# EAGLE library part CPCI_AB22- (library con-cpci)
Compact PCI AB 22 Source: www.erni.com
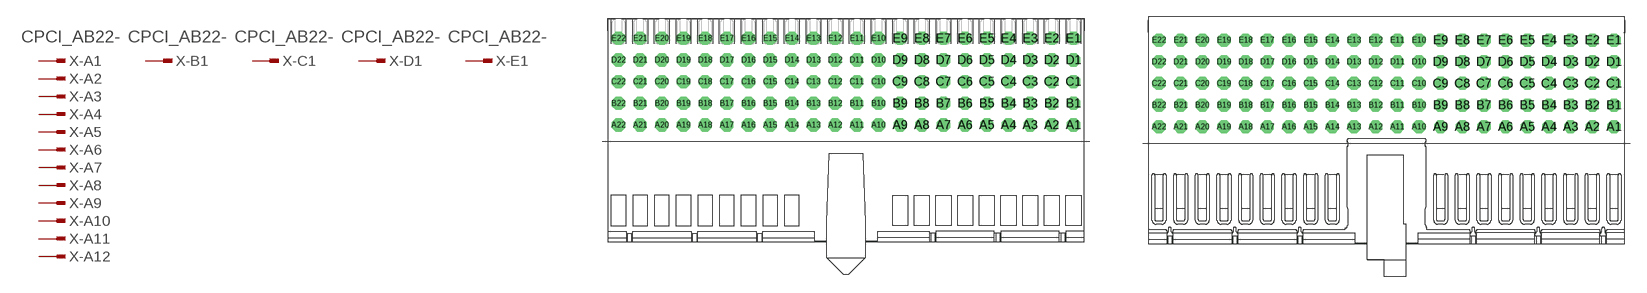
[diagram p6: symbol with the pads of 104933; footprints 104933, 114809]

Designator prefix X; gates -A1=PINV -B1=PINV -C1=PINV -D1=PINV -E1=PINV -A2=PIN -A3=PIN -A4=PIN -A5=PIN -A6=PIN -A7=PIN -A8=PIN -A9=PIN -A10=PIN -A11=PIN -A12=PIN -A13=PIN -A14=PIN -A15=PIN -A16=PIN -A17=PIN -A18=PIN -A19=PIN -A20=PIN -A21=PIN -A22=PIN -B2=PIN -B3=PIN -B4=PIN -B5=PIN -B6=PIN -B7=PIN -B8=PIN -B9=PIN -B10=PIN -B11=PIN -B12=PIN -B13=PIN -B14=PIN -B15=PIN -B16=PIN -B17=PIN -B18=PIN -B19=PIN -B20=PIN -B21=PIN -B22=PIN -C2=PIN -C3=PIN -C4=PIN -C5=PIN -C6=PIN -C7=PIN -C8=PIN -C9=PIN -C10=PIN -C11=PIN -C12=PIN -C13=PIN -C14=PIN -C15=PIN -C16=PIN -C17=PIN -C18=PIN -C19=PIN -C20=PIN -C21=PIN -C22=PIN -D2=PIN -D3=PIN -D4=PIN -D5=PIN -D6=PIN -D7=PIN -D8=PIN -D9=PIN -D10=PIN -D11=PIN -D12=PIN -D13=PIN -D14=PIN -D15=PIN -D16=PIN -D17=PIN -D18=PIN -D19=PIN -D20=PIN -D21=PIN -D22=PIN -E2=PIN -E3=PIN -E4=PIN -E5=PIN -E6=PIN -E7=PIN -E8=PIN -E9=PIN -E10=PIN -E11=PIN -E12=PIN -E13=PIN -E14=PIN -E15=PIN -E16=PIN -E17=PIN -E18=PIN -E19=PIN -E20=PIN -E21=PIN -E22=PIN

## CPCI_AB22-104933  [104933]
A1  -A1:1  in
A2  -A2:1  in
A3  -A3:1  in
A4  -A4:1  in
A5  -A5:1  in
A6  -A6:1  in
A7  -A7:1  in
A8  -A8:1  in
A9  -A9:1  in
A10  -A10:1  in
A11  -A11:1  in
A12  -A12:1  in
A13  -A13:1  in
A14  -A14:1  in
A15  -A15:1  in
A16  -A16:1  in
A17  -A17:1  in
A18  -A18:1  in
A19  -A19:1  in
A20  -A20:1  in
A21  -A21:1  in
A22  -A22:1  in
B1  -B1:1  in
B2  -B2:1  in
B3  -B3:1  in
B4  -B4:1  in
B5  -B5:1  in
B6  -B6:1  in
B7  -B7:1  in
B8  -B8:1  in
B9  -B9:1  in
B10  -B10:1  in
B11  -B11:1  in
B12  -B12:1  in
B13  -B13:1  in
B14  -B14:1  in
B15  -B15:1  in
B16  -B16:1  in
B17  -B17:1  in
B18  -B18:1  in
B19  -B19:1  in
B20  -B20:1  in
B21  -B21:1  in
B22  -B22:1  in
C1  -C1:1  in
C2  -C2:1  in
C3  -C3:1  in
C4  -C4:1  in
C5  -C5:1  in
C6  -C6:1  in
C7  -C7:1  in
C8  -C8:1  in
C9  -C9:1  in
C10  -C10:1  in
C11  -C11:1  in
C12  -C12:1  in
C13  -C13:1  in
C14  -C14:1  in
C15  -C15:1  in
C16  -C16:1  in
C17  -C17:1  in
C18  -C18:1  in
C19  -C19:1  in
C20  -C20:1  in
C21  -C21:1  in
C22  -C22:1  in
D1  -D1:1  in
D2  -D2:1  in
D3  -D3:1  in
D4  -D4:1  in
D5  -D5:1  in
D6  -D6:1  in
D7  -D7:1  in
D8  -D8:1  in
D9  -D9:1  in
D10  -D10:1  in
D11  -D11:1  in
D12  -D12:1  in
D13  -D13:1  in
D14  -D14:1  in
D15  -D15:1  in
D16  -D16:1  in
D17  -D17:1  in
D18  -D18:1  in
D19  -D19:1  in
D20  -D20:1  in
D21  -D21:1  in
D22  -D22:1  in
E1  -E1:1  in
E2  -E2:1  in
E3  -E3:1  in
E4  -E4:1  in
E5  -E5:1  in
E6  -E6:1  in
E7  -E7:1  in
E8  -E8:1  in
E9  -E9:1  in
E10  -E10:1  in
E11  -E11:1  in
E12  -E12:1  in
E13  -E13:1  in
E14  -E14:1  in
E15  -E15:1  in
E16  -E16:1  in
E17  -E17:1  in
E18  -E18:1  in
E19  -E19:1  in
E20  -E20:1  in
E21  -E21:1  in
E22  -E22:1  in

## CPCI_AB22-114809  [114809]
Pads as for 104933

## Footprint 104933 (pad centres in mm)
ERmet Federleiste AB 22 / ERmet Female Type AB 22 Source: http://www.erni.com/DB/PDF-Drawing/ERmet/104933.pdf
drill 0.7 pad 1.016 octagon: A1 21,1.5; A2 19,1.5; A3 17,1.5; A4 15,1.5; A5 13,1.5; A6 11,1.5; A7 9,1.5; A8 7,1.5; A9 5,1.5; A10 3,1.5; A11 1,1.5; A12 -1,1.5; A13 -3,1.5; A14 -5,1.5; A15 -7,1.5; A16 -9,1.5; A17 -11,1.5; A18 -13,1.5; A19 -15,1.5; A20 -17,1.5; A21 -19,1.5; A22 -21,1.5; B1 21,3.5; B2 19,3.5; B3 17,3.5; B4 15,3.5; B5 13,3.5; B6 11,3.5; B7 9,3.5; B8 7,3.5; B9 5,3.5; B10 3,3.5; B11 1,3.5; B12 -1,3.5; B13 -3,3.5; B14 -5,3.5; B15 -7,3.5; B16 -9,3.5; B17 -11,3.5; B18 -13,3.5; B19 -15,3.5; B20 -17,3.5; B21 -19,3.5; B22 -21,3.5; C1 21,5.5; C2 19,5.5; C3 17,5.5; C4 15,5.5; C5 13,5.5; C6 11,5.5; C7 9,5.5; C8 7,5.5; C9 5,5.5; C10 3,5.5; C11 1,5.5; C12 -1,5.5; C13 -3,5.5; C14 -5,5.5; C15 -7,5.5; C16 -9,5.5; C17 -11,5.5; C18 -13,5.5; C19 -15,5.5; C20 -17,5.5; C21 -19,5.5; C22 -21,5.5; D1 21,7.5; D2 19,7.5; D3 17,7.5; D4 15,7.5; D5 13,7.5; D6 11,7.5; D7 9,7.5; D8 7,7.5; D9 5,7.5; D10 3,7.5; D11 1,7.5; D12 -1,7.5; D13 -3,7.5; D14 -5,7.5; D15 -7,7.5; D16 -9,7.5; D17 -11,7.5; D18 -13,7.5; D19 -15,7.5; D20 -17,7.5; D21 -19,7.5; D22 -21,7.5; E1 21,9.5; E2 19,9.5; E3 17,9.5; E4 15,9.5; E5 13,9.5; E6 11,9.5; E7 9,9.5; E8 7,9.5; E9 5,9.5; E10 3,9.5; E11 1,9.5; E12 -1,9.5; E13 -3,9.5; E14 -5,9.5; E15 -7,9.5; E16 -9,9.5; E17 -11,9.5; E18 -13,9.5; E19 -15,9.5; E20 -17,9.5; E21 -19,9.5; E22 -21,9.5

## Footprint 114809 (pad centres in mm)
ERmet Federleiste AB 22 / ERmet Female Type AB 22 Source: http://www.erni.com/DB/PDF-Drawing/ERmet/114809.pdf
drill 0.7 pad 1.016 octagon: A1 189,-71.5; A2 187,-71.5; A3 185,-71.5; A4 183,-71.5; A5 181,-71.5; A6 179,-71.5; A7 177,-71.5; A8 175,-71.5; A9 173,-71.5; A10 171,-71.5; A11 169,-71.5; A12 167,-71.5; A13 165,-71.5; A14 163,-71.5; A15 161,-71.5; A16 159,-71.5; A17 157,-71.5; A18 155,-71.5; A19 153,-71.5; A20 151,-71.5; A21 149,-71.5; A22 147,-71.5; B1 189,-69.5; B2 187,-69.5; B3 185,-69.5; B4 183,-69.5; B5 181,-69.5; B6 179,-69.5; B7 177,-69.5; B8 175,-69.5; B9 173,-69.5; B10 171,-69.5; B11 169,-69.5; B12 167,-69.5; B13 165,-69.5; B14 163,-69.5; B15 161,-69.5; B16 159,-69.5; B17 157,-69.5; B18 155,-69.5; B19 153,-69.5; B20 151,-69.5; B21 149,-69.5; B22 147,-69.5; C1 189,-67.5; C2 187,-67.5; C3 185,-67.5; C4 183,-67.5; C5 181,-67.5; C6 179,-67.5; C7 177,-67.5; C8 175,-67.5; C9 173,-67.5; C10 171,-67.5; C11 169,-67.5; C12 167,-67.5; C13 165,-67.5; C14 163,-67.5; C15 161,-67.5; C16 159,-67.5; C17 157,-67.5; C18 155,-67.5; C19 153,-67.5; C20 151,-67.5; C21 149,-67.5; C22 147,-67.5; D1 189,-65.5; D2 187,-65.5; D3 185,-65.5; D4 183,-65.5; D5 181,-65.5; D6 179,-65.5; D7 177,-65.5; D8 175,-65.5; D9 173,-65.5; D10 171,-65.5; D11 169,-65.5; D12 167,-65.5; D13 165,-65.5; D14 163,-65.5; D15 161,-65.5; D16 159,-65.5; D17 157,-65.5; D18 155,-65.5; D19 153,-65.5; D20 151,-65.5; D21 149,-65.5; D22 147,-65.5; E1 189,-63.5; E2 187,-63.5; E3 185,-63.5; E4 183,-63.5; E5 181,-63.5; E6 179,-63.5; E7 177,-63.5; E8 175,-63.5; E9 173,-63.5; E10 171,-63.5; E11 169,-63.5; E12 167,-63.5; E13 165,-63.5; E14 163,-63.5; E15 161,-63.5; E16 159,-63.5; E17 157,-63.5; E18 155,-63.5; E19 153,-63.5; E20 151,-63.5; E21 149,-63.5; E22 147,-63.5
